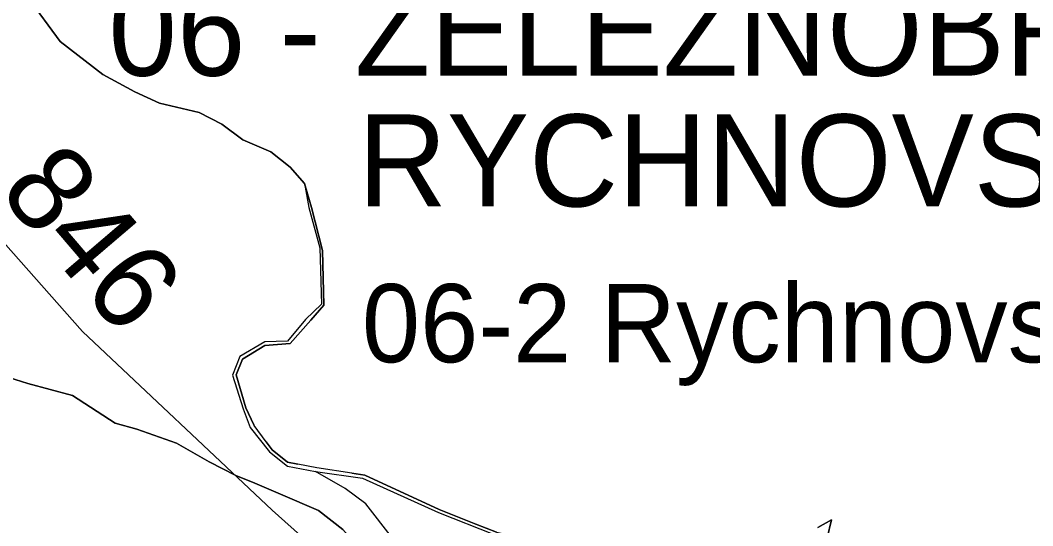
# Model space of a CAD drawing. Extents: x -689422 to -684666, y -987725 to -982160.
# Drawn here: x -686340 to -685241, y -985153 to -984604 of the extents above; entities that cross this region are included whole.
import ezdxf

# ---------------------------------------------------------------- set-up
doc = ezdxf.new("R2010")
doc.units = 0
for name, color, linetype in [('Dalkovy migracni koridor', 7, 'Continuous'), ('Dalkovy migracni koridor popis', 7, 'Continuous'), ('Hranice KC popis', 7, 'Continuous'), ('Hranice krajin popis', 7, 'Continuous'), ('Hranice obce', 7, 'Continuous'), ('KN_Hranice_katastrální území', 7, 'Continuous'), ('KN_hranice_parcel', 7, 'Continuous'), ('Krajina lesozemedelska - 5M2', 7, 'Continuous'), ('Migracne vyznamne uzemi', 7, 'Continuous')]:
    doc.layers.add(name, color=color, linetype=linetype)

msp = doc.modelspace()

# ---------------------------------------------------------------- linework, layer by layer
at = {"layer": 'Dalkovy migracni koridor'}
msp.add_lwpolyline([(-688139.26, -983735.17), (-687747.33, -983981.27), (-687574.42, -984063.16), (-687356.83, -984199.52), (-687115.06, -984393.75), (-686806.8, -984510.69), (-686662.36, -984565.48), (-686467.65, -984722.39), (-686272.89, -984942.15), (-686066.71, -985136.38), (-685714.12, -985451.58), (-685605.61, -985548.59), (-685554.26, -985606.87)], dxfattribs=at)
at = {"layer": 'Hranice obce'}
for points in [[(-685823.28, -985160.29), (-685845.59, -985151.38), (-685885.47, -985135.47), (-685966.32, -985098.25), (-685980.12, -985096.13), (-686018.35, -985090.26), (-686039.03, -985086.15), (-686050.11, -985083.94), (-686066.9, -985070.8), (-686073.32, -985062.02), (-686086.29, -985044.27), (-686086.7, -985043.71), (-686095.23, -985025.03), (-686105.78, -984989.1), (-686098.88, -984972.22), (-686074.81, -984957.49), (-686047.34, -984955.09), (-686024.79, -984929.71), (-686010.49, -984913.57), (-686011.97, -984854.28), (-686023.96, -984807.56), (-686031.7, -984781.35), (-686047.15, -984763.55), (-686068.34, -984746.87), (-686098.55, -984733.96), (-686121.31, -984716.98), (-686145.96, -984704.44), (-686189.16, -984694.3), (-686215.99, -984681.78), (-686250.63, -984662.81), (-686297.04, -984627.12), (-686332.28, -984578.95)], [(-685468.03, -985183.13), (-685459.33, -985146.91), (-685474.26, -985155.26)]]:
    msp.add_lwpolyline(points, dxfattribs=at)
at = {"layer": 'KN_Hranice_katastrální území'}
for points in [[(-685823.28, -985160.29), (-685845.59, -985151.38), (-685885.47, -985135.47), (-685966.32, -985098.25), (-685980.12, -985096.13), (-686018.35, -985090.26), (-686039.03, -985086.15), (-686050.11, -985083.94), (-686066.9, -985070.8), (-686073.32, -985062.02), (-686086.29, -985044.27), (-686086.7, -985043.71), (-686095.23, -985025.03), (-686105.78, -984989.1), (-686098.88, -984972.22), (-686074.81, -984957.49), (-686047.34, -984955.09), (-686024.79, -984929.71), (-686010.49, -984913.57), (-686011.97, -984854.28), (-686023.96, -984807.56), (-686031.7, -984781.35), (-686047.15, -984763.55), (-686068.34, -984746.87), (-686098.55, -984733.96), (-686121.31, -984716.98), (-686145.96, -984704.44), (-686189.16, -984694.3), (-686215.99, -984681.78), (-686250.63, -984662.81), (-686297.04, -984627.12), (-686332.28, -984578.95)], [(-685989.93, -985157.4), (-686016.57, -985136.68), (-686057.69, -985118.81), (-686085.72, -985107.05), (-686106.23, -985098.69), (-686135.06, -985083.64), (-686170.71, -985063.5), (-686213.87, -985048.17), (-686237.44, -985041.87), (-686283.67, -985011.67), (-686332.17, -984998.74), (-686373.71, -984985.8)], [(-686373.71, -984985.8), (-686332.17, -984998.74), (-686283.67, -985011.67), (-686237.44, -985041.87), (-686213.87, -985048.17), (-686170.71, -985063.5), (-686135.06, -985083.64), (-686106.23, -985098.69), (-686085.72, -985107.05), (-686057.69, -985118.81), (-686016.57, -985136.68), (-685989.93, -985157.4)], [(-685468.03, -985183.13), (-685459.33, -985146.91), (-685474.26, -985155.26)]]:
    msp.add_lwpolyline(points, dxfattribs=at)
at = {"layer": 'KN_hranice_parcel'}
for p, q in [((-686031.7, -984781.35), (-686023.96, -984807.56)), ((-686073.32, -985062.02), (-686086.29, -985044.27)), ((-685987.38, -985112.9), (-686019.85, -985094.09)), ((-685980.12, -985096.13), (-685966.32, -985098.25)), ((-685474.26, -985155.26), (-685459.33, -985146.91)), ((-685459.33, -985146.91), (-685468.03, -985183.13))]:
    msp.add_line(p, q, dxfattribs=at)
for points in [[(-686332.28, -984578.95), (-686297.04, -984627.12), (-686250.63, -984662.81), (-686215.99, -984681.78), (-686189.16, -984694.3), (-686145.96, -984704.44), (-686121.31, -984716.98), (-686098.55, -984733.96), (-686068.34, -984746.87), (-686047.15, -984763.55), (-686031.7, -984781.35)], [(-686031.7, -984781.35), (-686027.08, -984807.56), (-686015.15, -984851.27), (-686013.37, -984912.46), (-686030.44, -984929.21), (-686050.17, -984952.6), (-686074.72, -984953.5), (-686102.04, -984969.23), (-686109.69, -984989.76), (-686098.42, -985026.25), (-686090.49, -985046.54), (-686069.72, -985072.8), (-686050.27, -985088.6), (-686019.85, -985094.09)], [(-686023.96, -984807.56), (-686011.97, -984854.28), (-686010.49, -984913.57), (-686024.79, -984929.71), (-686047.34, -984955.09), (-686074.81, -984957.49), (-686098.88, -984972.22), (-686105.78, -984989.1), (-686095.23, -985025.03), (-686086.7, -985043.71), (-686086.29, -985044.27)], [(-685696.59, -985467.81), (-685711.12, -985429.26), (-685769.19, -985354.95), (-685817.11, -985312.74), (-685878.49, -985260.87), (-685908, -985237.21), (-685936.03, -985212.21), (-685954.98, -985198.48), (-685973.47, -985176.07), (-685989.93, -985157.4), (-686016.57, -985136.68), (-686057.69, -985118.81), (-686085.72, -985107.05), (-686106.23, -985098.69), (-686135.06, -985083.64), (-686170.71, -985063.5), (-686213.87, -985048.17), (-686237.44, -985041.87), (-686283.67, -985011.67), (-686332.17, -984998.74), (-686373.71, -984985.8)], [(-685696.59, -985467.81), (-685711.12, -985429.26), (-685769.19, -985354.95), (-685817.11, -985312.74), (-685878.49, -985260.87), (-685908, -985237.21), (-685936.03, -985212.21), (-685954.98, -985198.48), (-685973.47, -985176.07), (-685989.93, -985157.4), (-686016.57, -985136.68), (-686057.69, -985118.81), (-686085.72, -985107.05), (-686106.23, -985098.69), (-686135.06, -985083.64), (-686170.71, -985063.5), (-686213.87, -985048.17), (-686237.44, -985041.87), (-686283.67, -985011.67), (-686332.17, -984998.74), (-686373.71, -984985.8)], [(-686073.32, -985062.02), (-686066.9, -985070.8), (-686050.11, -985083.94), (-686039.03, -985086.15)], [(-685980.12, -985096.13), (-686018.35, -985090.26), (-686039.03, -985086.15)], [(-686019.85, -985094.09), (-685968.81, -985101.57), (-685886.13, -985138.79), (-685825.52, -985162.65), (-685798.67, -985167.95), (-685769.08, -985182.25), (-685737.67, -985204.87)], [(-685966.32, -985098.25), (-685885.47, -985135.47), (-685845.59, -985151.38)], [(-685700.63, -985321.41), (-685718.82, -985278.32), (-685785.05, -985239.06), (-685835.45, -985213.77), (-685896.14, -985194.22), (-685936.03, -985166.83), (-685965.12, -985129.37), (-685987.38, -985112.9)], [(-685845.59, -985151.38), (-685823.28, -985160.29), (-685798.34, -985165.45), (-685765.51, -985180.21), (-685734.87, -985202.01)]]:
    msp.add_lwpolyline(points, dxfattribs=at)
at = {"layer": 'Krajina lesozemedelska - 5M2'}
for points in [[(-685823.28, -985160.29), (-685845.59, -985151.38), (-685885.47, -985135.47), (-685966.32, -985098.25), (-685980.12, -985096.13), (-686018.35, -985090.26), (-686039.03, -985086.15), (-686050.11, -985083.94), (-686066.9, -985070.8), (-686073.32, -985062.02), (-686086.29, -985044.27), (-686086.7, -985043.71), (-686095.23, -985025.03), (-686105.78, -984989.1), (-686098.88, -984972.22), (-686074.81, -984957.49), (-686047.34, -984955.09), (-686024.79, -984929.71), (-686010.49, -984913.57), (-686011.97, -984854.28), (-686023.96, -984807.56), (-686031.7, -984781.35), (-686047.15, -984763.55), (-686068.34, -984746.87), (-686098.55, -984733.96), (-686121.31, -984716.98), (-686145.96, -984704.44), (-686189.16, -984694.3), (-686215.99, -984681.78), (-686250.63, -984662.81), (-686297.04, -984627.12), (-686332.28, -984578.95)], [(-685468.03, -985183.13), (-685459.33, -985146.91), (-685474.26, -985155.26)]]:
    msp.add_lwpolyline(points, dxfattribs=at)
at = {"layer": 'Migracne vyznamne uzemi'}
msp.add_lwpolyline([(-685823.28, -985160.29), (-685845.59, -985151.38), (-685885.47, -985135.47), (-685966.32, -985098.25), (-685980.12, -985096.13), (-686018.35, -985090.26), (-686039.03, -985086.15), (-686050.11, -985083.94), (-686066.9, -985070.8), (-686073.32, -985062.02), (-686086.29, -985044.27), (-686086.7, -985043.71), (-686095.23, -985025.03), (-686105.78, -984989.1), (-686098.88, -984972.22), (-686074.81, -984957.49), (-686047.34, -984955.09), (-686024.79, -984929.71), (-686010.49, -984913.57), (-686011.97, -984854.28), (-686023.96, -984807.56), (-686031.7, -984781.35), (-686047.15, -984763.55), (-686068.34, -984746.87), (-686098.55, -984733.96), (-686121.31, -984716.98), (-686145.96, -984704.44), (-686189.16, -984694.3), (-686215.99, -984681.78), (-686250.63, -984662.81), (-686297.04, -984627.12), (-686332.28, -984578.95)], dxfattribs=at)

# ---------------------------------------------------------------- texts
at = {"layer": 'Dalkovy migracni koridor popis'}
msp.add_text('846', height=93.75, rotation=310.49536, dxfattribs=at).set_placement((-686365.55, -984790.53))
at = {"layer": 'Hranice KC popis'}
for s, p in [('06 - ŽELEZNOBRODSKO,', (-686244.53, -984664.3)), ('RYCHNOVSKO', (-685973.52, -984806.36))]:
    msp.add_text(s, height=100, dxfattribs=at).set_placement(p)
at = {"layer": 'Hranice krajin popis'}
msp.add_text('06-2 Rychnovsko', height=85, dxfattribs=at).set_placement((-685969.33, -984975.6))

doc.saveas('drawing.dxf')
